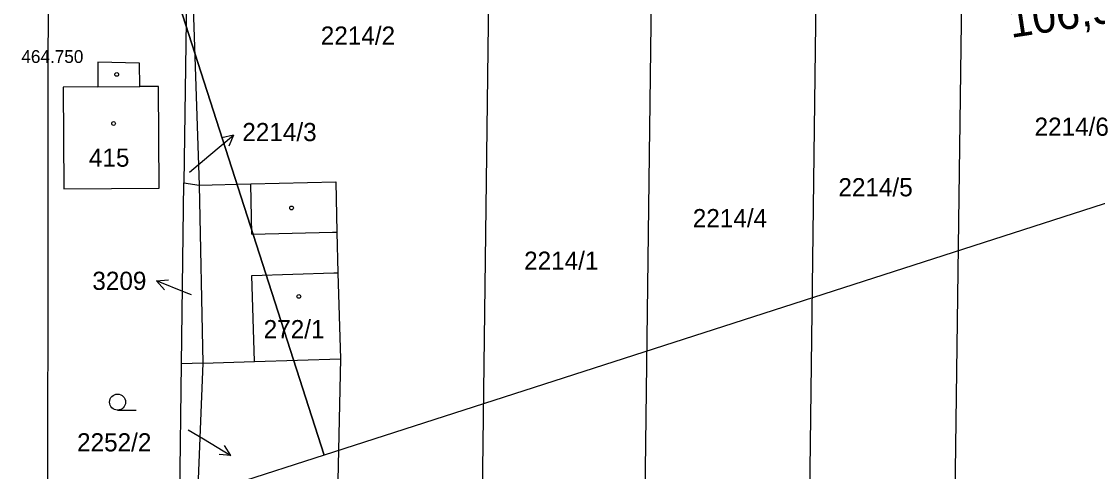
# Model space of a CAD drawing. Extents: x -758836 to -757729, y -1175316 to -1174366.
# Drawn here: x -758200.5 to -758099.9, y -1174833.7 to -1174791.7 of the extents above; entities that cross this region are included whole.
import ezdxf

# ---------------------------------------------------------------- set-up
doc = ezdxf.new("R2010")
doc.units = 0
for name, color, linetype in [('_NOR-pomocná', 7, 'Continuous'), ('_NOR-popis', 7, 'Continuous'), ('Hranice parcel', 7, 'Continuous'), ('Parcelní čísla', 7, 'Continuous'), ('Pop  PČ popisy', 7, 'Continuous'), ('Vnitřní kresba', 7, 'Continuous'), ('Vrstva 61', 7, 'Continuous'), ('Značky budov', 7, 'Continuous'), ('Značky kultur', 7, 'Continuous')]:
    doc.layers.add(name, color=color, linetype=linetype)

msp = doc.modelspace()

# ---------------------------------------------------------------- linework, layer by layer
at = {"layer": '_NOR-pomocná'}
for points in [[(-758217.71, -1174690.84), (-758117.77, -1174658.65), (-758072.24, -1174800), (-758172.18, -1174832.19)], [(-758317.65, -1174723.03), (-758217.71, -1174690.84), (-758172.18, -1174832.19), (-758272.12, -1174864.38)]]:
    msp.add_lwpolyline(points, close=True, dxfattribs=at)
at = {"layer": 'Hranice parcel'}
for p, q in [((-758143.14, -1174911.79), (-758141.37, -1174774.78)), ((-758127.73, -1174911.25), (-758125.97, -1174774.42)), ((-758114.13, -1174910.8), (-758112.36, -1174774.1)), ((-758156.63, -1174775.13), (-758157.87, -1174870.96)), ((-758184.92, -1174776.46), (-758185.31, -1174806.74)), ((-758184.92, -1174776.46), (-758183.9, -1174806.95)), ((-758185.53, -1174823.65), (-758185.31, -1174806.74)), ((-758185.31, -1174806.74), (-758183.9, -1174806.95)), ((-758183.9, -1174806.95), (-758183.53, -1174823.59)), ((-758170.66, -1174823.2), (-758171.67, -1174870.63)), ((-758186.22, -1174876.87), (-758185.53, -1174823.65)), ((-758183.53, -1174823.59), (-758185.73, -1174876.96)), ((-758183.53, -1174823.59), (-758185.53, -1174823.65))]:
    msp.add_line(p, q, dxfattribs=at)
for points in [[(-758198.02, -1174777.55), (-758198.11, -1174871.18), (-758198.12, -1174878.49)], [(-758196.6, -1174797.79), (-758196.54, -1174807.31), (-758187.63, -1174807.24), (-758187.69, -1174797.73), (-758189.45, -1174797.74), (-758189.47, -1174795.54), (-758193.37, -1174795.47), (-758193.36, -1174797.77), (-758196.6, -1174797.79)], [(-758183.9, -1174806.95), (-758179.06, -1174806.83), (-758171.11, -1174806.65), (-758171, -1174811.35), (-758170.9, -1174815.15), (-758170.66, -1174823.2)], [(-758183.53, -1174823.59), (-758178.71, -1174823.44), (-758170.66, -1174823.2)]]:
    msp.add_lwpolyline(points, dxfattribs=at)
at = {"layer": 'Pop  PČ popisy'}
for p, q in [((-758182.97, -1174804.2), (-758180.67, -1174802.27)), ((-758180.67, -1174802.27), (-758181.76, -1174802.53)), ((-758180.67, -1174802.27), (-758181.12, -1174803.3)), ((-758184.79, -1174805.73), (-758182.97, -1174804.2)), ((-758187.87, -1174815.9), (-758186.76, -1174815.81)), ((-758185.09, -1174817.02), (-758187.87, -1174815.9)), ((-758187.87, -1174815.9), (-758187.13, -1174816.74)), ((-758184.59, -1174817.22), (-758185.09, -1174817.02)), ((-758184.9, -1174829.84), (-758183.49, -1174830.69)), ((-758183.49, -1174830.69), (-758180.92, -1174832.24)), ((-758180.92, -1174832.24), (-758181.52, -1174831.29)), ((-758180.92, -1174832.24), (-758182.03, -1174832.15))]:
    msp.add_line(p, q, dxfattribs=at)
at = {"layer": 'Vnitřní kresba'}
for p, q in [((-758193.36, -1174797.77), (-758189.45, -1174797.74)), ((-758178.95, -1174811.53), (-758179.06, -1174806.83)), ((-758178.95, -1174811.53), (-758171.4, -1174811.36)), ((-758171.4, -1174811.36), (-758171, -1174811.35)), ((-758178.95, -1174815.39), (-758171.3, -1174815.16)), ((-758171.3, -1174815.16), (-758170.9, -1174815.15)), ((-758178.71, -1174823.44), (-758178.95, -1174815.39))]:
    msp.add_line(p, q, dxfattribs=at)
at = {"layer": 'Značky budov'}
for centre in [(-758191.6, -1174796.6), (-758191.89, -1174801.19), (-758175.24, -1174809.09), (-758174.56, -1174817.36)]:
    msp.add_circle(centre, 0.175, dxfattribs=at)
at = {"layer": 'Značky kultur'}
msp.add_line((-758191.52, -1174827.99), (-758189.77, -1174827.99), dxfattribs=at)
msp.add_circle((-758191.52, -1174827.24), 0.75, dxfattribs=at)

# ---------------------------------------------------------------- texts
at = {"layer": '_NOR-popis'}
msp.add_text('106,5', height=3, rotation=8.6527, dxfattribs=at).set_placement((-758107.95, -1174793.19))
at = {"layer": 'Parcelní čísla'}
for s, p in [('2214/2', (-758172.51, -1174793.82)), ('2214/3', (-758179.85, -1174802.84)), ('2214/6', (-758105.74, -1174802.34)), ('415', (-758194.2, -1174805.23)), ('2214/5', (-758124.09, -1174808)), ('2214/4', (-758137.71, -1174810.89)), ('2214/1', (-758153.49, -1174814.87)), ('3209', (-758193.88, -1174816.75)), ('272/1', (-758177.85, -1174821.27)), ('2252/2', (-758195.31, -1174831.85))]:
    msp.add_text(s, height=1.7, dxfattribs=at).set_placement(p)
at = {"layer": 'Vrstva 61'}
msp.add_text('464.750', height=1.2, dxfattribs=at).set_placement((-758200.52, -1174795.53))

doc.saveas('drawing.dxf')
